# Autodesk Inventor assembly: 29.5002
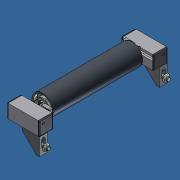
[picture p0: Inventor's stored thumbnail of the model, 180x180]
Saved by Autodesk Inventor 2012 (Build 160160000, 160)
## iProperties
Created: 2007-07
Part Number: 29.5002
Document SubType Name: Assembly
Designer: Andy Moles
Description: SUPPORT ROLLER KIT
Vendor: S
Author: Andy Moles
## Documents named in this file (7)
- Y:\INVENTOR LIBRARIES\PARTS LIBRARY\BELT AND ROLLER CONVEYORS\29.5002 SUPPORT ROLLER KIT.iam
- Y:\INVENTOR LIBRARIES\PARTS LIBRARY\BELT AND ROLLER CONVEYORS\SUBCOMPONENTS\29.5002 SUPPORT ROLLER KIT PVC TUBE.ipt
- Y:\INVENTOR LIBRARIES\PARTS LIBRARY\BELT AND ROLLER CONVEYORS\21.1722 BEARING ASSEMBLY S.iam
- Y:\INVENTOR LIBRARIES\PARTS LIBRARY\BELT AND ROLLER CONVEYORS\SUBCOMPONENTS\29.5002 SUPPORT ROLLER KIT 32X32.ipt
- Y:\INVENTOR LIBRARIES\PARTS LIBRARY\BELT AND ROLLER CONVEYORS\SUBCOMPONENTS\29.5002 SUPPORT ROLLER KIT 8mm ROD.ipt
- Y:\INVENTOR LIBRARIES\PARTS LIBRARY\END CAPS\22.1002_1 END CAP 32X32 Z GRAY.iam
- Y:\INVENTOR LIBRARIES\PARTS LIBRARY\FASTENING ELEMENTS\21.2078 Angle 19 GD-Z.iam
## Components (12 placed, 6 different names)
1. 29.5002 SUPPORT ROLLER KIT PVC TUBE:1 — Mate:1, Mate:2, Mate:3, Insert:1, Insert:2, Mate:8, Mate:23, Mate:24
2. 21.1722 BEARING ASSEMBLY S:1 [sub-assembly] — Insert:1, Angle:2
3. 21.1722 BEARING ASSEMBLY S:2 [sub-assembly] — Insert:2, Angle:1
4. 29.5002 SUPPORT ROLLER KIT 32X32:1 — Flush:1, Flush:2, Mate:15, Flush:16, Flush:17, Mate:16, Flush:18, Flush:19, Mate:19, Mate:22, Angle:2, Mate:24
5. 29.5002 SUPPORT ROLLER KIT 32X32:2 — Mate:6, Flush:3, Mate:17, Flush:20, Flush:21, Mate:18, Flush:22, Flush:23, Mate:20, Mate:21, Angle:1, Mate:23
6. 29.5002 SUPPORT ROLLER KIT 8mm ROD:1 — Mate:7, Mate:8
7. 21.2078 Angle 19 GD-Z:1 [sub-assembly] — Mate:20, Flush:26, Mate:21
8. 21.2078 Angle 19 GD-Z:2 [sub-assembly] — Mate:19, Flush:25, Mate:22
9. 22.1002_1 END CAP 32X32 Z GRAY:1 [sub-assembly] — Mate:15, Flush:16, Flush:17
10. 22.1002_1 END CAP 32X32 Z GRAY:2 [sub-assembly] — Mate:16, Flush:18, Flush:19, Flush:25
11. 22.1002_1 END CAP 32X32 Z GRAY:3 [sub-assembly] — Mate:17, Flush:20, Flush:21, Flush:26
12. 22.1002_1 END CAP 32X32 Z GRAY:4 [sub-assembly] — Mate:18, Flush:22, Flush:23
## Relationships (33: Mate 16, Flush 13, Insert 2, Angle 2)
- Mate:1: 29.5002 SUPPORT ROLLER KIT PVC TUBE:1
- Mate:2: 29.5002 SUPPORT ROLLER KIT PVC TUBE:1
- Mate:3: 29.5002 SUPPORT ROLLER KIT PVC TUBE:1
- Insert:1: 29.5002 SUPPORT ROLLER KIT PVC TUBE:1 ↔ 21.1722 BEARING ASSEMBLY S:1
- Insert:2: 29.5002 SUPPORT ROLLER KIT PVC TUBE:1 ↔ 21.1722 BEARING ASSEMBLY S:2
- Flush:1: 29.5002 SUPPORT ROLLER KIT 32X32:1
- Flush:2: 29.5002 SUPPORT ROLLER KIT 32X32:1
- Mate:6: 29.5002 SUPPORT ROLLER KIT 32X32:2
- Flush:3: 29.5002 SUPPORT ROLLER KIT 32X32:2
- Mate:7: 29.5002 SUPPORT ROLLER KIT 8mm ROD:1
- Mate:8: 29.5002 SUPPORT ROLLER KIT PVC TUBE:1 ↔ 29.5002 SUPPORT ROLLER KIT 8mm ROD:1
- Mate:15: 29.5002 SUPPORT ROLLER KIT 32X32:1 ↔ 22.1002_1 END CAP 32X32 Z GRAY:1
- Flush:16: 29.5002 SUPPORT ROLLER KIT 32X32:1 ↔ 22.1002_1 END CAP 32X32 Z GRAY:1
- Flush:17: 29.5002 SUPPORT ROLLER KIT 32X32:1 ↔ 22.1002_1 END CAP 32X32 Z GRAY:1
- Mate:16: 29.5002 SUPPORT ROLLER KIT 32X32:1 ↔ 22.1002_1 END CAP 32X32 Z GRAY:2
- Flush:18: 29.5002 SUPPORT ROLLER KIT 32X32:1 ↔ 22.1002_1 END CAP 32X32 Z GRAY:2
- Flush:19: 29.5002 SUPPORT ROLLER KIT 32X32:1 ↔ 22.1002_1 END CAP 32X32 Z GRAY:2
- Mate:17: 29.5002 SUPPORT ROLLER KIT 32X32:2 ↔ 22.1002_1 END CAP 32X32 Z GRAY:3
- Flush:20: 29.5002 SUPPORT ROLLER KIT 32X32:2 ↔ 22.1002_1 END CAP 32X32 Z GRAY:3
- Flush:21: 29.5002 SUPPORT ROLLER KIT 32X32:2 ↔ 22.1002_1 END CAP 32X32 Z GRAY:3
- Mate:18: 29.5002 SUPPORT ROLLER KIT 32X32:2 ↔ 22.1002_1 END CAP 32X32 Z GRAY:4
- Flush:22: 29.5002 SUPPORT ROLLER KIT 32X32:2 ↔ 22.1002_1 END CAP 32X32 Z GRAY:4
- Flush:23: 29.5002 SUPPORT ROLLER KIT 32X32:2 ↔ 22.1002_1 END CAP 32X32 Z GRAY:4
- Mate:19: 29.5002 SUPPORT ROLLER KIT 32X32:1 ↔ 21.2078 Angle 19 GD-Z:2
- Flush:25: 21.2078 Angle 19 GD-Z:2 ↔ 22.1002_1 END CAP 32X32 Z GRAY:2
- Mate:20: 29.5002 SUPPORT ROLLER KIT 32X32:2 ↔ 21.2078 Angle 19 GD-Z:1
- Flush:26: 21.2078 Angle 19 GD-Z:1 ↔ 22.1002_1 END CAP 32X32 Z GRAY:3
- Mate:21: 29.5002 SUPPORT ROLLER KIT 32X32:2 ↔ 21.2078 Angle 19 GD-Z:1
- Mate:22: 29.5002 SUPPORT ROLLER KIT 32X32:1 ↔ 21.2078 Angle 19 GD-Z:2
- Angle:1: 21.1722 BEARING ASSEMBLY S:2 ↔ 29.5002 SUPPORT ROLLER KIT 32X32:2
- Angle:2: 21.1722 BEARING ASSEMBLY S:1 ↔ 29.5002 SUPPORT ROLLER KIT 32X32:1
- Mate:23: 29.5002 SUPPORT ROLLER KIT PVC TUBE:1 ↔ 29.5002 SUPPORT ROLLER KIT 32X32:2
- Mate:24: 29.5002 SUPPORT ROLLER KIT PVC TUBE:1 ↔ 29.5002 SUPPORT ROLLER KIT 32X32:1
